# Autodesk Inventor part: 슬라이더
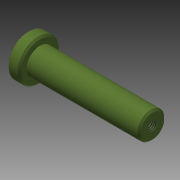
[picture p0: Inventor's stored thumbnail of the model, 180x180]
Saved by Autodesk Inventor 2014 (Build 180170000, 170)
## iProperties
Created: 2011-04
Part Number: 슬라이더
Document SubType Name: Modeling
Density: 1 g/cm^3
Material: 일반
Appearance: 올리브 녹색
Author: pww
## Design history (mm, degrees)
sketch "스케치1"
  geometry: L1 (-7, 0)-(63, 0); L2 (63, 0)-(63, 7.5); L3 (63, 7.5)-(0, 7.5); L4 (-7, 0)-(-7, 11.5); L5 (-7, 11.5)-(0, 11.5); L6 (0, 11.5)-(0, 7.5); 1 further point
  constraints: 12 end point, 3 perpendicular, 2 horizontal, 2 point on line, 1 parallel
  dimensions: "d1" = 70 distance of L1.start L1.end; "d19" = 15 diameter of L3 L1; "d20" = 7 distance of L4.end L5.end; "d21" = 23 diameter of L5 L1
revolve "회전1" stored, may be unused: angle "d4" = 90 deg
chamfer "모따기1" distance "d16" = 1; stored, may be unused: second distance "d17" = 2, angle "d18" = 45 deg
hole "구멍2" diameter "d24" = 4.917; stored, may be unused: countersink angle "d28" = 90 deg, drill point angle "d30" = 118 deg; dims "d22" = 10, "d23" = 10, "d25" = 10, "d26" = 4, "d27" = 2, "d29" = 13
node "솔리드1"
